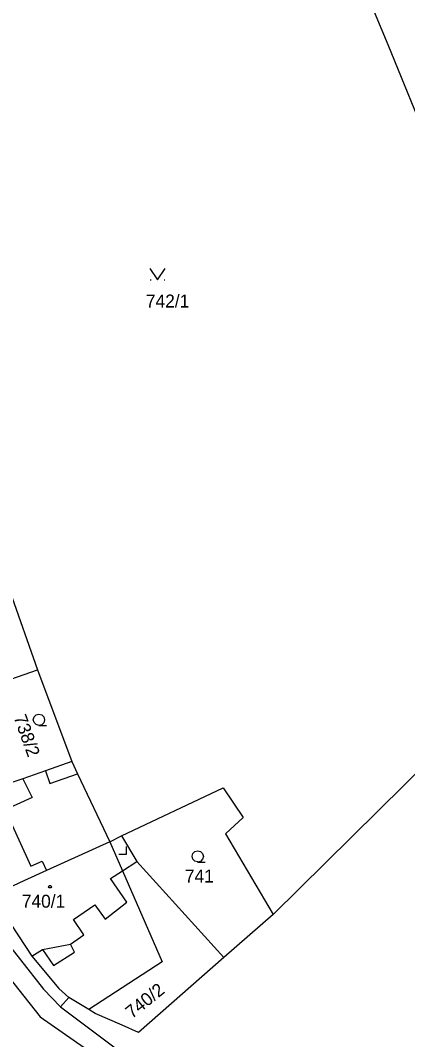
# Model space of a CAD drawing. Extents: x -621797 to -620972, y -1175539 to -1174697.
# Drawn here: x -621256.4 to -621205.7, y -1175396.7 to -1175263 of the extents above; entities that cross this region are included whole.
import ezdxf

# ---------------------------------------------------------------- set-up
doc = ezdxf.new("R2010")
doc.units = 0
for name, color, linetype in [('Rozvod plynu EON', 7, 'Continuous'), ('SDEL EON', 7, 'Continuous'), ('SDEL EON - popis', 7, 'Continuous'), ('Silnoproud EON', 7, 'Continuous'), ('Silnoproud EON - popis', 7, 'Continuous')]:
    doc.layers.add(name, color=color, linetype=linetype)

msp = doc.modelspace()

# ---------------------------------------------------------------- linework, layer by layer
at = {"layer": 'Rozvod plynu EON'}
msp.add_lwpolyline([(-621252.46, -1175376.51), (-621252.37, -1175376.66), (-621252.46, -1175376.81), (-621252.64, -1175376.81), (-621252.73, -1175376.66), (-621252.64, -1175376.51)], close=True, dxfattribs=at)
at = {"layer": 'SDEL EON'}
for p, q in [((-621239.4, -1175297.05), (-621239.3, -1175297.05)), ((-621237.6, -1175297.05), (-621237.5, -1175297.05))]:
    msp.add_line(p, q, dxfattribs=at)
for points in [[(-621239.45, -1175295.55), (-621238.45, -1175297.05), (-621237.45, -1175295.55)], [(-621253.99, -1175355.5), (-621254.37, -1175355.4), (-621254.64, -1175355.13), (-621254.74, -1175354.76), (-621254.64, -1175354.39), (-621254.37, -1175354.12), (-621254, -1175354.02), (-621253.63, -1175354.12), (-621253.36, -1175354.39), (-621253.26, -1175354.77), (-621253.36, -1175355.15), (-621253.63, -1175355.42), (-621254.01, -1175355.52), (-621253.01, -1175355.52)], [(-621243.53, -1175372.38), (-621242.53, -1175372.38), (-621242.53, -1175371.38)], [(-621233.18, -1175373.41), (-621233.56, -1175373.31), (-621233.83, -1175373.04), (-621233.93, -1175372.67), (-621233.83, -1175372.3), (-621233.56, -1175372.03), (-621233.19, -1175371.93), (-621232.82, -1175372.03), (-621232.55, -1175372.3), (-621232.45, -1175372.68), (-621232.55, -1175373.06), (-621232.82, -1175373.33), (-621233.2, -1175373.43), (-621232.2, -1175373.43)]]:
    msp.add_lwpolyline(points, dxfattribs=at)
at = {"layer": 'SDEL EON - popis'}
for p, q in [((-621253.16, -1175361.45), (-621252.58, -1175363.11)), ((-621252.58, -1175363.11), (-621248.94, -1175361.83)), ((-621256.13, -1175362.49), (-621254.88, -1175364.95)), ((-621254.88, -1175364.95), (-621258.42, -1175366.56)), ((-621258.42, -1175366.56), (-621255.05, -1175373.95)), ((-621255.05, -1175373.95), (-621253.59, -1175373.29)), ((-621253.59, -1175373.29), (-621253.01, -1175374.55)), ((-621243.06, -1175374.57), (-621241.15, -1175373.33)), ((-621244.61, -1175375.58), (-621243.06, -1175374.57)), ((-621242.46, -1175378.7), (-621244.61, -1175375.58)), ((-621260.15, -1175377.84), (-621254.94, -1175385.75)), ((-621249.48, -1175380.97), (-621246.69, -1175379.02)), ((-621246.69, -1175379.02), (-621245.32, -1175380.93)), ((-621245.32, -1175380.93), (-621242.46, -1175378.7)), ((-621264.73, -1175380.01), (-621253.83, -1175393.72)), ((-621248.13, -1175382.95), (-621249.48, -1175380.97)), ((-621249.88, -1175384.21), (-621248.13, -1175382.95)), ((-621253.55, -1175384.89), (-621249.88, -1175384.21)), ((-621249.32, -1175385.24), (-621249.88, -1175384.21)), ((-621254.94, -1175385.75), (-621253.55, -1175384.89)), ((-621254.94, -1175385.75), (-621251.41, -1175390.02)), ((-621253.55, -1175384.89), (-621252.09, -1175387.01)), ((-621252.09, -1175387.01), (-621249.32, -1175385.24)), ((-621251.41, -1175390.02), (-621250.09, -1175391.18)), ((-621253.83, -1175393.72), (-621243.98, -1175400.59))]:
    msp.add_line(p, q, dxfattribs=at)
at = {"layer": 'Silnoproud EON'}
for p, q in [((-621218.73, -1175240.96), (-621208.28, -1175266.18)), ((-621208.28, -1175266.18), (-621191.91, -1175306.3)), ((-621257.8, -1175337.9), (-621254.17, -1175348.21)), ((-621179.26, -1175336.75), (-621223.31, -1175380.29)), ((-621261.69, -1175350.84), (-621254.17, -1175348.21)), ((-621254.17, -1175348.21), (-621249.69, -1175360.24)), ((-621249.69, -1175360.24), (-621253.16, -1175361.45)), ((-621249.69, -1175360.24), (-621248.94, -1175361.83)), ((-621253.16, -1175361.45), (-621256.13, -1175362.49)), ((-621248.94, -1175361.83), (-621244.72, -1175370.77)), ((-621256.13, -1175362.49), (-621257.55, -1175362.98)), ((-621243.18, -1175369.97), (-621229.83, -1175363.67)), ((-621229.83, -1175363.67), (-621227.21, -1175367.56)), ((-621227.21, -1175367.56), (-621229.56, -1175369.74)), ((-621244.72, -1175370.77), (-621243.18, -1175369.97)), ((-621243.18, -1175369.97), (-621241.15, -1175373.33)), ((-621229.56, -1175369.74), (-621223.31, -1175380.29)), ((-621244.72, -1175370.77), (-621253.01, -1175374.55)), ((-621244.72, -1175370.77), (-621243.06, -1175374.57)), ((-621241.15, -1175373.33), (-621229.78, -1175385.96)), ((-621253.01, -1175374.55), (-621255.97, -1175375.9)), ((-621243.06, -1175374.57), (-621237.86, -1175386.5)), ((-621255.97, -1175375.9), (-621260.15, -1175377.84)), ((-621262.21, -1175378.9), (-621253.4, -1175390.1)), ((-621223.31, -1175380.29), (-621229.78, -1175385.96)), ((-621229.78, -1175385.96), (-621240.95, -1175395.77)), ((-621237.86, -1175386.5), (-621247.48, -1175392.75)), ((-621253.4, -1175390.1), (-621251.18, -1175392.43)), ((-621250.09, -1175391.18), (-621251.18, -1175392.43)), ((-621247.48, -1175392.75), (-621250.09, -1175391.18)), ((-621251.18, -1175392.43), (-621242.79, -1175398.69)), ((-621246.62, -1175393.27), (-621247.48, -1175392.75)), ((-621243.07, -1175394.82), (-621246.62, -1175393.27)), ((-621240.95, -1175395.77), (-621243.07, -1175394.82))]:
    msp.add_line(p, q, dxfattribs=at)

# ---------------------------------------------------------------- texts
at = {"layer": 'Silnoproud EON - popis'}
for s, p in [('742/1', (-621239.983, -1175300.68)), ('741', (-621234.873, -1175376.11)), ('740/1', (-621256.243, -1175379.41))]:
    msp.add_text(s, height=1.7, dxfattribs=at).set_placement(p)
for s, rotation, p in [('738/2', 289.80205, (-621257.34, -1175354.433)), ('740/2', 38.67465, (-621241.807, -1175394.043))]:
    msp.add_text(s, height=1.7, rotation=rotation, dxfattribs=at).set_placement(p)

doc.saveas('drawing.dxf')
